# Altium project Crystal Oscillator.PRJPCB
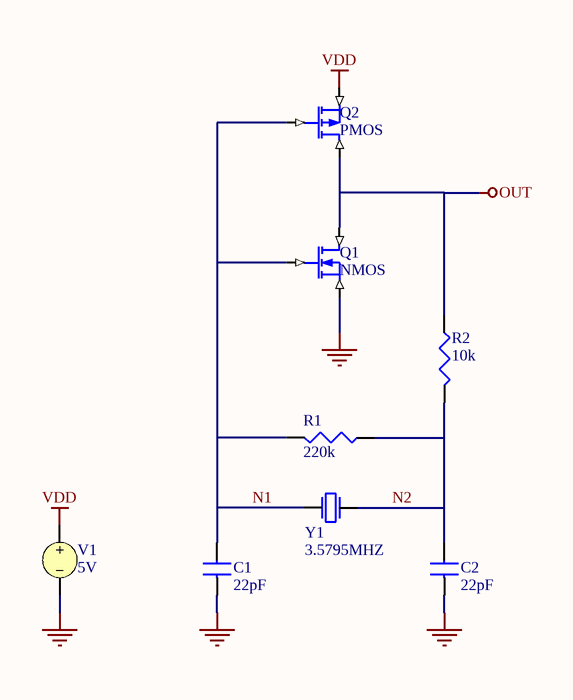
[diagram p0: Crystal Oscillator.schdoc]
1 sheet, 8 parts. Net scope: global (net labels, ports and power ports of the same name join across sheets).

## Sheet Crystal Oscillator.schdoc: Crystal Oscillator
size A4; Organization: Altium Limited; Address1: L3, 12a Rodborough Rd; Address2: Frenchs Forest; Address3: NSW; Address4: Australia 2086; DocumentNumber: 1; SheetNumber: 1; SheetTotal: 1

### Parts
C1  22pF
C2  22pF
Q1  NMOS
Q2  PMOS
R1  220k
R2  10k
V1  5V
Y1  3.5795MHZ

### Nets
GND: C1.1 C2.1 Q1.3(S) V1.2
OUT: Q1.1(D) Q2.1(D) R2.2(BOT)
VDD: Q2.3(S) V1.1
N1: C1.2 Q1.2(G) Q2.2(G) R1.1(TOP) Y1.1(P1)
N2: C2.2 R1.2(BOT) R2.1(TOP) Y1.2(P2)

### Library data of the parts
C1 C2 = CAP: Capacitor
Q1 = NMOS: N-Channel MOSFET
Q2 = PMOS: P-Channel MOSFET
R1 R2 = RES: Resistor
V1 = VSRC: Voltage Source
Y1 = 3.5795MHZ: Crystal Oscillator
